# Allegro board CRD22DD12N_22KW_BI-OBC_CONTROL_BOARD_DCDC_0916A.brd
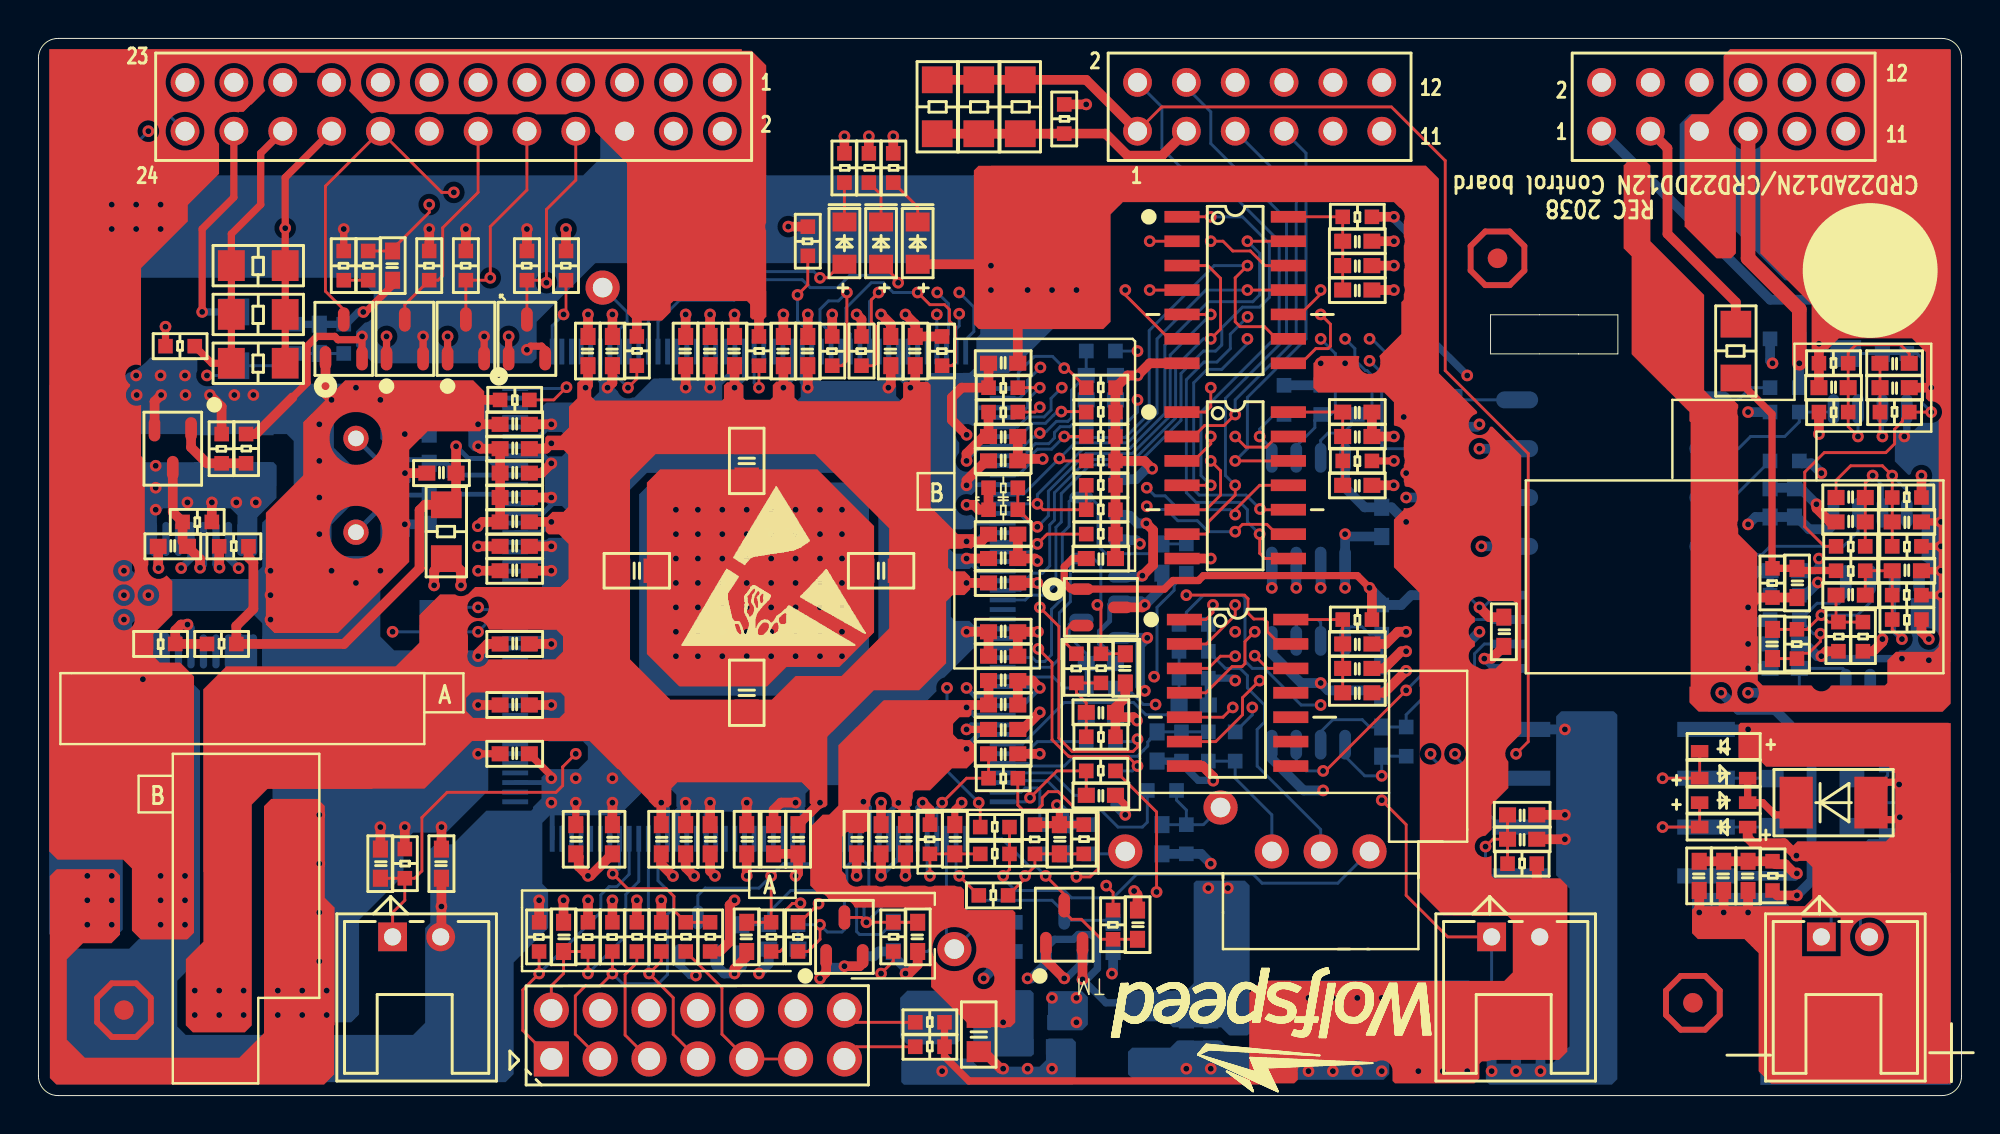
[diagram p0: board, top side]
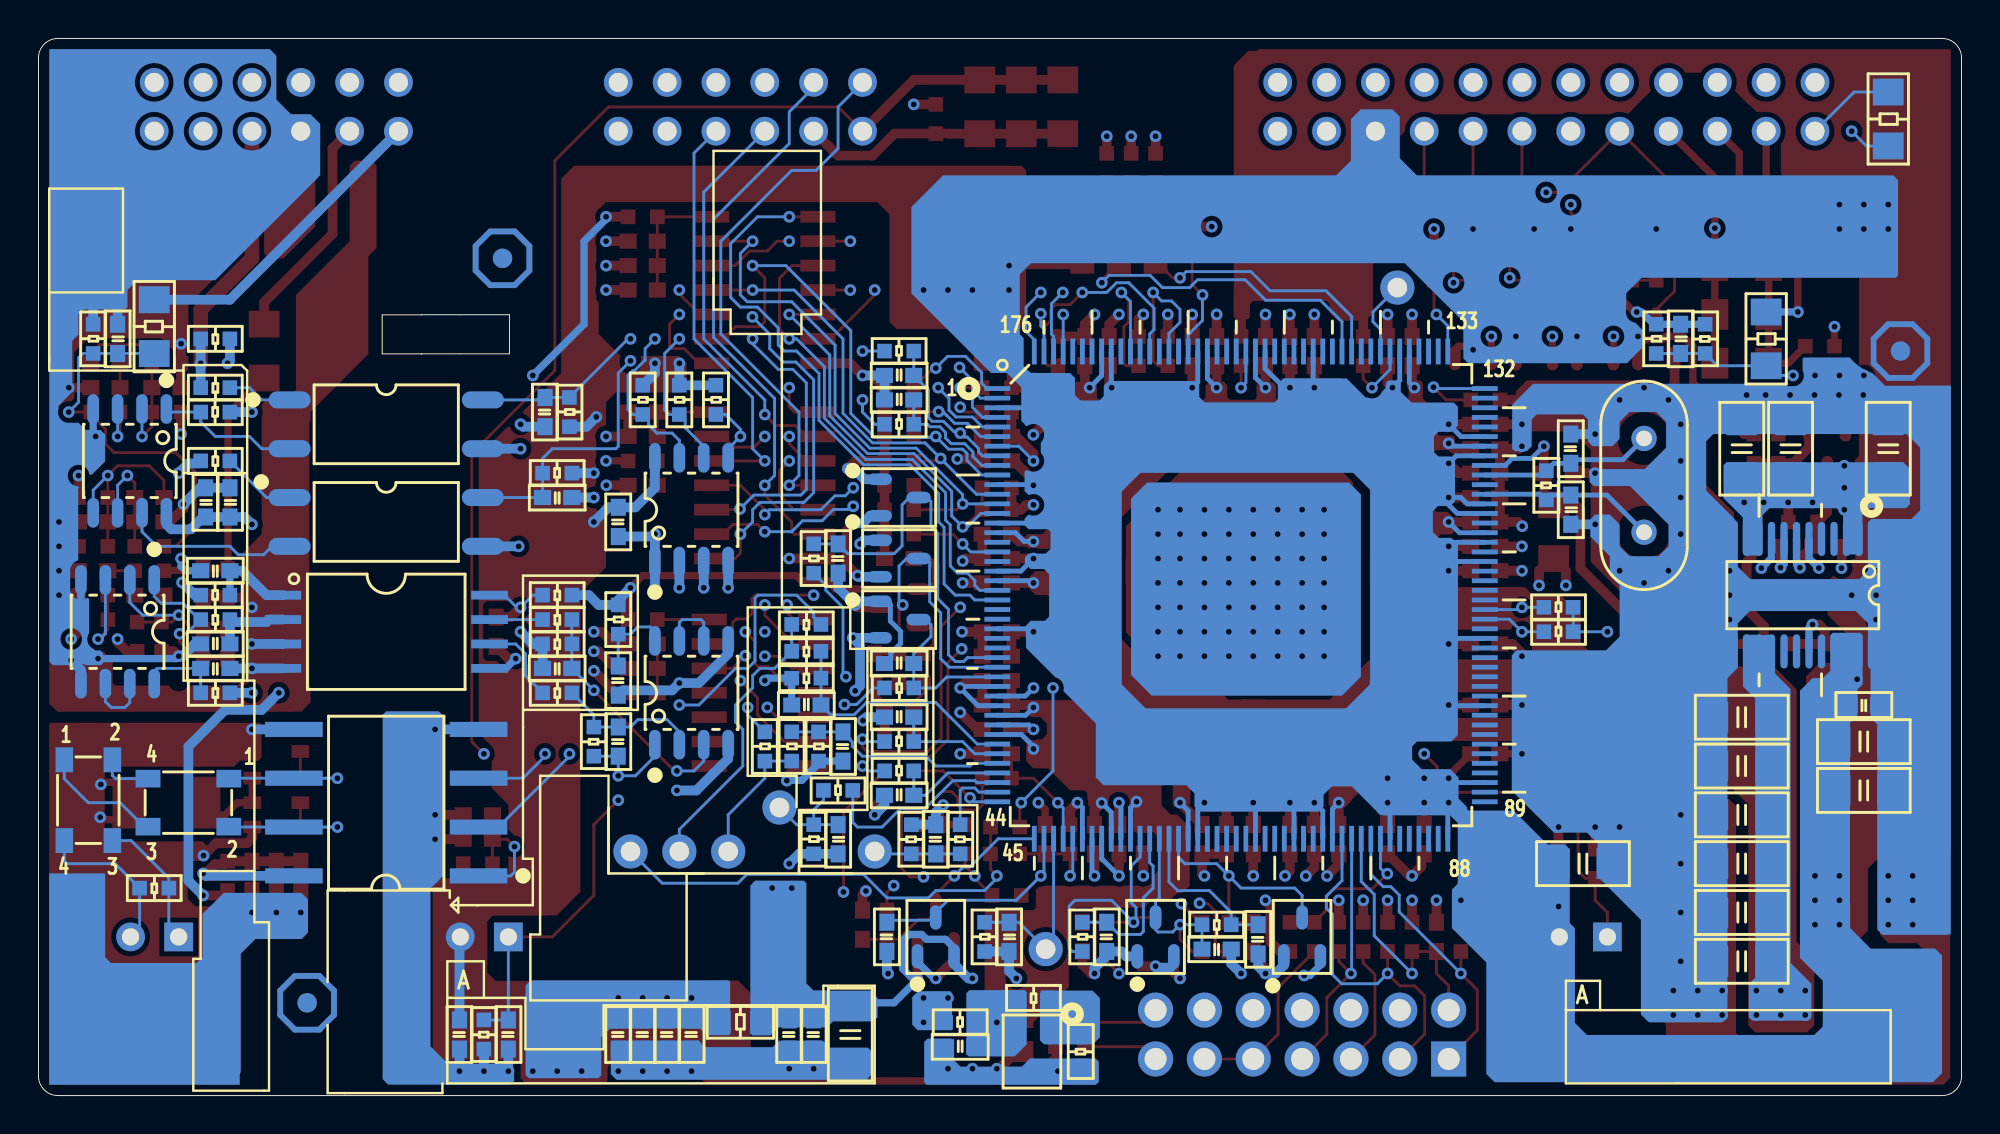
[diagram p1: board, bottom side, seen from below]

Outline 100 x 55 mm; copper layers: TOP, ART02, ART03, BOTTOM. Coordinates in mm from the lower left corner of the outline.
Outline path: 0,53.98 0,1.02 arc(0.3,0.3) 1.02,0 98.98,0 arc(99.7,0.3) 100,1.02 100,53.98 arc(99.7,54.7) 98.98,55 1.02,55 arc(0.3,54.7) 0,53.98 ; 75.51,40.62 80.08,40.62 80.08,40.62 82.13,40.62 82.13,38.59 80.08,38.59 80.08,38.59 75.51,38.59 75.51,40.62

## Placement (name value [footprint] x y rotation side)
AB  TP  [1MMTESTPOINT]  64.14 12.7 0 top
BC  TP  [1MMTESTPOINT]  66.67 12.7 0 top
C237  22n  [C0603]  91.44 26.67 90 top
C254  0.022n  [C0603]  20.32 30.48 90 bottom
C371  0.022n  [C0603]  20.32 33.66 270 bottom
C378  0.1u  [C0603]  27.3 8.26 90 top
C392  0.12n  [C0603]  50.16 34.29 0 top
C393  2.2n  [C0603]  55.24 15.62 0 bottom
C396  0.1u  [C0603]  69.85 29.84 270 bottom
C397  680p  [C0603]  52.07 2.54 0 bottom
C398  0.1u  [C0603]  69.85 3.17 270 bottom
C399  0.1u  [C0603]  68.58 3.17 270 bottom
C400  0.1u  [C0603]  67.31 3.17 270 bottom
C401  0.1u  [C0603]  66.04 3.17 270 bottom
C402  0.1u  [C0603]  60.96 3.17 270 bottom
C403  0.1u  [C0603]  59.69 3.17 270 bottom
C404  4.7u  [C1206]  57.78 3.17 270 bottom
C405  1u  [C0603]  78.11 3.17 270 bottom
C406  1u  [C0603]  20.95 12.06 270 top
C407  0.47u  [C0603]  75.56 3.17 270 bottom
C408  0.47u  [C0603]  55.24 22.48 0 bottom
C409  0.47u  [C0603]  17.78 12.06 90 top
C410  0.47u  [C0603]  58.42 27.94 270 bottom
C445  0.1u  [C0603]  90.81 27.3 180 bottom
C446  2.2n  [C0603]  90.81 23.5 0 bottom
C447  0.1u  [C0603]  76.2 24.13 90 top
C448  0.33n  [C0603]  73.03 22.23 180 bottom
C449  0.33n  [C0603]  69.85 18.41 270 bottom
C451  0.47u  [C0603]  69.85 21.59 270 bottom
C452  4.7n  [C0603]  57.15 8.89 90 top
C453  0.15n  [C0603]  97.16 27.3 180 top
C454  0.15n  [C0603]  94.23 26.04 180 top
C455  0.15n  [C0603]  90.17 23.5 270 top
C457  0.47u  [C0603]  90.81 22.23 180 bottom
C458  0.47n  [C0603]  96.52 36.83 0 top
C459  0.1u  [C0603]  93.34 36.83 180 top
C460  0.15n  [C0603]  96.52 38.1 0 top
C462  0.47u  [C0603]  90.04 30.86 90 bottom
C463  0.12n  [C0603]  73.66 35.56 270 bottom
C464  0.12n  [C0603]  73.03 31.11 180 bottom
C465  0.47n  [C0603]  94.23 29.84 180 top
C466  0.15n  [C0603]  94.23 31.11 180 top
C467  0.12n  [C0603]  97.16 29.84 0 top
C471  1u  [C0603]  77.15 14.61 0 top
C472  0.1u  [C0603]  77.15 13.34 0 top
C473  1u  [C0603]  86.36 11.43 270 top
C474  0.1u  [C0603]  88.9 11.43 270 top
C475  0.01u  [C0603]  87.63 11.43 270 top
C488  2.2n  [C0603]  53.09 13.34 90 top
C489  4.7n  [C0603]  55.88 8.26 270 bottom
C492  0.01u  [C0603]  55.24 19.94 0 top
C493  0.01u  [C0603]  56.52 22.23 270 top
C494  0.1u  [C0603]  55.24 27.94 0 top
C496  10u  [C1206]  11.43 33.66 90 bottom
C497  10u  [C1206]  8.89 33.66 90 bottom
C499  0.1u  [C0603]  5.08 20.32 180 bottom
C500  10u  [C1206]  5.08 18.41 180 bottom
C501  10u  [C1206]  5.08 15.88 180 bottom
C504  10u  [C1206]  3.81 33.66 90 bottom
C505  0.1u  [C0603]  6.99 28.57 180 top
C506  10u  [C1206]  19.68 12.06 180 bottom
C507  10u  [C1206]  11.43 14.61 0 bottom
C508  10u  [C1206]  11.43 12.06 0 bottom
C509  10u  [C1206]  11.43 17.14 0 bottom
C510  10u  [C1206]  11.43 9.53 0 bottom
C511  10u  [C1206]  11.43 6.99 0 bottom
C512  2.2u  [C0805]  36.83 33.02 270 top
C513  2.2u  [C0805]  43.81 27.3 180 top
C514  2.2u  [C0805]  36.83 20.95 90 top
C515  2.2u  [C0805]  31.11 27.3 0 top
C516  10u  [C1206]  11.43 19.68 0 bottom
C519  22n  [C0603]  20.95 32.38 180 top
C520  0.1u  [C0603]  50.16 38.1 180 top
C521  2.2u  [C0603]  50.16 19.05 0 top
C522  2.2u  [C0603]  45.59 38.73 270 top
C523  2.2u  [C0603]  44.32 38.73 270 top
C524  2.2u  [C0603]  40.01 38.73 270 top
C525  2.2u  [C0603]  38.73 38.73 270 top
C526  2.2u  [C0603]  36.2 38.73 270 top
C527  2.2u  [C0603]  34.92 38.73 270 top
C528  2.2u  [C0603]  33.66 38.73 270 top
C529  2.2u  [C0603]  29.84 38.73 270 top
C530  2.2u  [C0603]  28.57 38.73 270 top
C531  2.2u  [C0603]  24.77 34.92 180 top
C532  2.2u  [C0603]  24.77 33.66 180 top
C533  2.2u  [C0603]  24.77 32.38 180 top
C534  2.2u  [C0603]  24.77 31.11 180 top
C535  2.2u  [C0603]  24.77 29.84 180 top
C536  2.2u  [C0603]  24.77 28.57 180 top
C537  2.2u  [C0603]  24.77 27.3 180 top
C538  2.2u  [C0603]  24.77 23.5 180 top
C539  2.2u  [C0603]  24.77 20.32 180 top
C540  2.2u  [C0603]  24.77 17.78 180 top
C541  2.2u  [C0603]  27.94 13.34 90 top
C542  2.2u  [C0603]  29.84 13.34 90 top
C543  2.2u  [C0603]  32.38 13.34 90 top
C544  2.2u  [C0603]  33.66 13.34 90 top
C545  2.2u  [C0603]  34.92 13.34 90 top
C546  2.2u  [C0603]  36.83 13.34 90 top
C547  2.2u  [C0603]  38.23 13.34 90 top
C548  2.2u  [C0603]  39.5 13.34 90 top
C549  2.2u  [C0603]  45.09 13.34 90 top
C550  2.2u  [C0603]  43.81 13.34 90 top
C551  2.2u  [C0603]  42.55 13.34 90 top
C552  0.1u  [C0603]  50.16 22.86 0 top
C553  0.1u  [C0603]  50.16 33.02 180 top
C554  2.2u  [C0603]  50.16 29.21 180 top
C555  0.1u  [C0603]  50.16 27.94 180 top
C556  2.2u  [C0603]  50.16 26.67 180 top
C557  0.1u  [C0603]  50.16 24.13 180 top
C558  2.2u  [C0603]  50.16 21.59 180 top
C559  2.2u  [C0603]  50.16 20.32 180 top
C560  0.1u  [C0603]  68.58 35.56 0 top
C561  0.01u  [C0603]  68.58 31.75 0 top
C562  1u  [C0603]  68.58 34.29 0 top
C563  0.1u  [C0603]  68.58 23.5 0 top
C564  0.01u  [C0603]  68.58 20.95 0 top
C565  1u  [C0603]  68.58 22.23 0 top
C566  0.47u  [C0603]  91.31 30.86 90 bottom
C592  2.2u  [C0805]  48.9 3.17 270 top
C593  120p  [C0603]  45.72 8.26 270 top
C594  0.47n  [C0603]  95.89 39.37 90 bottom
C595  2.2n  [C0603]  44.45 8.26 270 bottom
C596  120p  [C0603]  38.73 7.62 180 bottom
C597  2.2n  [C0603]  36.58 8.13 270 bottom
C598  2.2n  [C0603]  55.24 15.62 0 top
C600  0.1u  [C0603]  68.58 43.18 0 top
C601  0.01u  [C0603]  68.58 41.91 0 top
C602  1u  [C0603]  68.58 44.45 0 top
C687  0.01u  [C0603]  49.53 8.26 90 bottom
C690  0.01u  [C0603]  53.34 13.34 270 bottom
C691  0.01u  [C0603]  58.42 13.34 90 bottom
C693  0.12n  [C0603]  55.24 36.2 0 bottom
C694  2.2n  [C0603]  55.24 19.68 0 bottom
C695  0.12n  [C0603]  55.24 37.47 0 bottom
C696  2.2n  [C0603]  50.16 17.78 0 top
C697  0.12n  [C0603]  18.41 43.18 270 top
C698  2.2n  [C0603]  14.61 39.37 90 bottom
C699  1n  [C0603]  36.83 8.26 270 top
C700  0.1u  [C0603]  60.07 20.32 0 bottom
C701  0.1u  [C0603]  58.17 18.16 270 bottom
C702  0.1u  [C0603]  47.65 13.34 90 top
CA  TP  [1MMTESTPOINT]  69.22 12.7 0 top
D84  BAV99  [SOT-23]  55.24 31.11 270 bottom
D85  BAV99  [SOT-23]  55.24 27.94 270 bottom
D86  BAV99  [SOT-23]  34.29 8.26 180 bottom
D89  BAV99  [SOT-23]  53.34 8.89 0 top
D90  BAV99  [SOT-23]  41.91 8.26 180 bottom
D92  BAV99  [SOT-23]  55.24 24.77 270 bottom
D95  BAV99  [SOT-23]  15.88 39.37 0 top
D102  RC-CL-170R-0805  [LED0805]  41.91 44.35 90 top
D103  RC-CL-170R-0805  [LED0805]  43.81 44.35 90 top
D104  RC-CL-170R-0805  [LED0805]  45.72 44.35 90 top
D110  BAS21WS-TP  [SOD-323]  87.63 13.97 180 top
D111  SMBJ15CA  [SMB]  93.34 15.24 180 top
D112  BAS21WS-TP  [SOD-323]  87.63 15.24 0 top
D113  BAS21WS-TP  [SOD-323]  87.63 17.91 180 top
D114  BAS21WS-TP  [SOD-323]  87.63 16.51 0 top
D115  BAV99  [SOT-23]  53.34 8.26 180 bottom
D124  BAV99  [SOT-23]  25.4 39.37 0 top
D125  BAV99  [SOT-23]  22.23 39.37 0 top
D126  BAV99  [SOT-23]  19.05 39.37 0 top
D127  BAV99  [SOT-23]  41.91 8.26 0 top
DAC_1  TP  [1MMTESTPOINT]  47.62 7.62 180 bottom
DAC_4  TP  [1MMTESTPOINT]  56.52 12.7 0 bottom
DAC_5  TP  [1MMTESTPOINT]  61.47 14.99 180 bottom
DAC_6  TP  [1MMTESTPOINT]  29.34 42.04 180 bottom
J2  PIN2*12-2.54-F  [CON_2MM54_12X2]  21.59 51.44 180 top
J3  PIN2*6-2.54-F  [CON_2MM54_6X2]  63.5 51.44 0 top
J4  PIN2*6-2.54-F  [CON_2MM54_6X2]  87.63 51.44 0 top
J5  2*7P 2.54  [CON_2MM54_7X2]  34.29 3.17 180 top
J11  XHB2.54-2P-F  [CON_2MM54_2X1]  92.71 8.26 180 top
J17  1*2P  [CONNECT_2MM54_2X1]  75.56 8.26 180 top
J18  1*2P  [CONNECT_2MM54_2X1]  18.41 8.26 180 top
L21  33uH 0.2A  [R0805]  63.5 3.81 0 bottom
NOREF  -  []  38.34 26.64 0 top
NOREF#2  #VAL  [unnamed#2]  4.45 4.45 0 top
NOREF#3  -  []  346.48 2.43 0 top
NOREF#4  -  []  95.25 42.93 0 top
NOREF#5  -  []  187.11 64.82 0 top
NOREF#6  -  []  1.02 0 90 top
NOREF#7  #VAL  [unnamed#2]  75.87 43.56 0 top
NOREF#8  -  []  0.01 -3.22 0 top
NOREF#9  -  []  280.71 1.57 0 top
NOREF#10  -  []  0.01 -5.17 0 top
NOREF#11  #VAL  [unnamed#2]  86.03 4.83 0 top
NOREF#12  -  []  2 -5 90 top
NOREF#13  #VAL  [unnamed#2]  3.17 38.73 180 bottom
NOREF#14  #VAL  [unnamed#2]  75.87 43.56 180 bottom
NOREF#15  #VAL  [unnamed#2]  86.03 4.83 180 bottom
Q1  2N7002/SOT  [SOT-23]  6.99 33.66 180 top
R49  620K  [R1206]  3.81 50.81 90 bottom
R58  24K  [R0603]  51.82 13.34 270 top
R133  12K  [R0603]  90.17 26.67 270 top
R221  1M  [R0603]  21.59 31.75 270 bottom
R327  1R  [R0603]  31.11 38.73 90 top
R400  1R  [R0603]  37.47 38.73 90 top
R404  10k  [R0603]  26.04 8.26 270 top
R405  10k  [R0603]  29.84 8.26 270 top
R406  10k  [R0603]  32.38 8.26 270 top
R407  10k  [R0603]  34.92 8.26 90 top
R408  0  [R0603]  33.66 8.26 90 top
R409  0  [R0603]  31.11 8.26 90 top
R410  470  [R0603]  28.57 8.26 270 top
R411  2.2k  [R0603]  46.35 3.81 180 top
R412  2.2k  [R0603]  46.35 2.54 180 top
R414  2k  [R0603]  55.24 34.29 180 top
R415  2k  [R0603]  55.24 33.02 180 top
R416  2k  [R0603]  55.24 30.48 180 top
R417  2k  [R0603]  50.16 30.48 0 top
R418  2k  [R0603]  41.27 38.73 270 top
R419  2k  [R0603]  40.01 44.45 270 top
R420  2k  [R0603]  46.99 38.73 270 top
R421  2k  [R0603]  42.8 38.73 270 top
R422  2k  [R0603]  55.24 29.21 180 top
R423  2k  [R0603]  55.24 36.83 180 top
R424  2k  [R0603]  50.16 36.83 0 top
R425  2k  [R0603]  55.24 35.56 180 top
R431  1k  [R0603]  50.16 35.56 0 top
R432  1k  [R0603]  55.24 16.89 0 bottom
R437  10k  [R0603]  64.77 36.2 90 bottom
R438  10k  [R0603]  66.67 36.2 90 bottom
R439  10k  [R0603]  68.58 36.2 90 bottom
R440  200  [R0603]  52.07 3.81 0 bottom
R441  1.5k  [R0603]  48.26 5.08 180 bottom
R442  4.7k  [R0603]  45.8 2.29 270 bottom
R443  2k  [R0603]  41.91 48.26 90 top
R444  2k  [R0603]  43.18 48.26 90 top
R445  2k  [R0603]  44.45 48.26 90 top
R446  10k  [R0603]  76.83 3.17 270 bottom
R447  3.3k  [R0603]  55.24 21.21 180 bottom
R448  10k  [R0603]  19.05 12.06 90 top
R449  3.3k  [R0603]  59.69 27.94 90 bottom
R482  2k  [R0603]  90.81 24.77 180 bottom
R483  10k  [R0603]  73.03 24.77 180 bottom
R484  10k  [R0603]  73.03 23.5 180 bottom
R485  10k  [R0603]  73.03 20.95 180 bottom
R486  10k  [R0603]  71.12 18.41 270 bottom
R487  2k  [R0603]  55.88 8.89 270 top
R488  150k  [R0603]  94.23 27.3 0 top
R489  100k  [R0603]  97.16 26.04 180 top
R491  100k  [R0603]  91.44 23.5 270 top
R492  1M  [R0603]  97.16 24.77 0 top
R493  1M  [R0603]  94.87 23.88 90 top
R494  150k  [R0603]  93.6 23.88 90 top
R495  2k  [R0603]  96.52 35.56 180 top
R496  2.2k  [R0603]  93.34 35.56 0 top
R497  2k  [R0603]  93.34 38.1 180 top
R500  3K  [R0603]  90.81 36.83 180 bottom
R502  3.9k  [R0603]  72.39 35.56 90 bottom
R503  3K  [R0603]  90.81 33.02 180 bottom
R505  3.9k  [R0603]  73.03 32.38 0 bottom
R506  1k  [R0603]  94.23 28.57 0 top
R507  15k  [R0603]  97.16 31.11 180 top
R508  4k  [R0603]  97.16 28.57 0 top
R514  620  [R0603]  20.95 24.13 0 bottom
R515  10k  [R0603]  20.95 25.4 0 bottom
R516  0  [R0603]  90.17 11.43 90 top
R517  120  [R0603]  93.98 10.79 180 bottom
R528  24k  [R0603]  54.36 13.34 90 top
R529  1k  [R0603]  49.66 10.41 180 top
R532  100  [R0603]  53.98 22.23 270 top
R533  470k  [R0603]  55.24 18.67 0 top
R534  3.3k  [R0603]  55.24 22.23 90 top
R536  10k  [R0603]  8.26 29.84 0 top
R537  1.5k  [R0603]  10.79 33.66 90 top
R538  12k  [R0603]  9.53 33.66 270 top
R540  100k  [R0603]  6.35 23.5 0 top
R541  0R  [R0603]  9.53 23.5 180 top
R546  10k  [R1206]  21.21 29.34 270 top
R547  0  [R0603]  10.16 28.57 180 top
R549  2.2R  [R0603]  68.58 33.02 0 top
R550  2.2R  [R0603]  68.58 24.77 0 top
R569  10k  [R0603]  90.81 35.56 0 bottom
R573  620k  [R1206]  88.27 38.73 270 top
R574  620k  [R1206]  93.98 40.01 270 bottom
R575  12K  [R0603]  97.16 39.37 90 bottom
R580  20R  [R1206]  51.05 51.44 90 top
R581  20R  [R1206]  48.9 51.44 90 top
R582  20R  [R1206]  46.74 51.44 90 top
R583  100  [R0603]  44.45 8.26 90 top
R588  0  [R0603]  53.34 50.81 90 top
R592  10R  [R0603]  90.81 20.95 180 bottom
R593  10R  [R0603]  90.81 26.04 0 bottom
R594  10R  [R0603]  73.03 26.04 180 bottom
R595  10R  [R0603]  69.85 24.77 90 bottom
R597  10R  [R0603]  90.81 39.37 180 bottom
R598  10R  [R0603]  77.15 12.06 180 top
R599  1k  [R0603]  45.72 8.26 90 bottom
R602  100  [R0603]  39.5 8.26 270 top
R603  20R  [R1206]  11.43 43.18 0 top
R604  20R  [R1206]  11.43 40.64 0 top
R605  20R  [R1206]  11.43 38.1 0 top
R606  1k  [R0603]  38.73 8.89 180 bottom
R607  1k  [R0603]  55.24 16.89 180 top
R608  1k  [R0603]  55.24 38.73 0 bottom
R610  2k  [R0603]  55.24 31.75 180 top
R611  2k  [R0603]  50.16 31.62 0 top
R612  2.2R  [R0603]  68.58 45.72 0 top
R673  100k  [R0603]  50.8 8.26 90 bottom
R678  1k  [R0603]  52.07 13.34 270 bottom
R679  1k  [R0603]  58.42 15.88 0 bottom
R680  100k  [R0603]  54.61 13.34 270 bottom
R681  100k  [R0603]  59.69 13.34 90 bottom
R683  1k  [R0603]  55.24 34.92 0 bottom
R684  1k  [R0603]  55.24 18.41 0 bottom
R685  10k  [R0603]  22.23 43.18 270 top
R686  1k  [R0603]  50.16 16.51 0 top
R687  10k  [R0603]  20.32 43.18 270 top
R688  10k  [R0603]  25.4 43.18 270 top
R689  1k  [R0603]  17.14 43.18 270 top
R691  10k  [R0603]  15.88 43.18 270 top
R692  24k  [R0603]  15.88 39.37 90 bottom
R693  1k  [R0603]  38.1 8.26 90 top
R694  620K  [R1206]  10.16 39.37 90 bottom
R695  24K  [R0603]  13.34 39.37 270 bottom
R696  1k  [R0603]  60.07 23.11 180 bottom
R697  NA  [R0603]  60.07 21.72 180 bottom
R698  1k  [R0603]  60.83 18.16 90 bottom
R699  NA  [R0603]  59.44 18.16 90 bottom
R700  1k  [R0603]  49.73 12.57 180 top
R701  NA  [R0603]  46.35 13.34 270 top
R702  0  [R0603]  7.37 38.99 180 top
R703  2k  [R0603]  27.43 43.18 270 top
R704  0R  [R0603]  60.07 24.51 180 bottom
R705  0R  [R0603]  49.73 13.97 180 top
R706  0R  [R0603]  62.23 18.16 90 bottom
R707  2k  [R0603]  24.77 36.2 0 top
T1  TRNSFMR TV105  [4532]  92.2 15.24 0 bottom
T2  TRNSFMR TV105  [4532]  97.41 15.37 270 bottom
U9  AZ431  [SOT23_1-32]  48.34 2.29 0 bottom
U28  TMS320F28377D  [LQFP176-050-2424]  37.47 26.04 270 bottom
U32  24C16BT-I/SN  [SOIC-8]  66.04 30.48 90 bottom
U43  ACPL-C870-500E  [SSO-8]  81.92 24.13 270 bottom
U44  OPA2376  [SOIC-8]  95.89 24.13 270 bottom
U45  OPA2376  [SOIC-8]  66.04 20.95 90 bottom
U48  LM2903  [SOIC-8]  95.25 33.02 270 bottom
U53  1050  [SO-G8]  81.92 15.24 0 bottom
U55  LM50CIM3  [SOT-23]  55.24 25.4 270 top
U57  TPS70445PWP_TSSOP24  [TSSOP24]  8.26 26.04 270 bottom
U58  MC74VHCT50A_SOIC14  [SOIC14]  62.23 31.75 0 top
U59  MC74VHCT50A_SOIC14  [SOIC14]  62.35 20.95 0 top
U60  -  [TCLT1003]  81.92 34.92 180 bottom
U61  -  [TCLT1003]  81.92 29.84 180 bottom
U62  MC74VHCT50A_SOIC14  [SOIC14]  62.23 41.91 0 top
Y1  HLX32 20MHz  [TSX-3225]  16.51 31.75 270 bottom

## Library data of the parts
AB BC CA DAC_1 DAC_4-DAC_6 = 1MMTESTPOINT: User Part Number: HAMP; Tolerance: #TOL
C237 C254 C371 C378 C392 C393 C396-C403 C405-C410 C445-C449 C451-C455 C457-C460 C462-C467 C471-C475 C488 C489 C492-C494 C499 C505 C519-C566 C593-C598 C600-C602 C687 C690 C691 C693-C702 = C0603: Tolerance: #TOL; User Part Number: HAMP
C404 C496 C497 C500 C501 C504 C506-C511 C516 = C1206: Tolerance: #TOL; User Part Number: HAMP
C512-C515 C592 = C0805: Tolerance: #TOL; User Part Number: HAMP
D84-D86 D89 D90 D92 D95 D115 D124-D127 Q1 U55 = SOT-23: Tolerance: #TOL; User Part Number: HAMP
D102-D104 = LED0805: Tolerance: #TOL; User Part Number: HAMP
D110 D112-D114 = SOD-323: Tolerance: #TOL; User Part Number: HAMP
D111 = SMB: Tolerance: #TOL; User Part Number: HAMP
J2 = CON_2MM54_12X2: Tolerance: #TOL; User Part Number: HAMP
J3 J4 = CON_2MM54_6X2: Tolerance: #TOL; User Part Number: HAMP
J5 = CON_2MM54_7X2: Tolerance: #TOL; User Part Number: HAMP
J11 = CON_2MM54_2X1: Tolerance: #TOL; User Part Number: HAMP
J17 J18 = CONNECT_2MM54_2X1: Tolerance: #TOL; User Part Number: HAMP
L21 = R0805: Tolerance: #TOL; User Part Number: HAMP
NOREF#2 NOREF#7 NOREF#11 NOREF#13-NOREF#15 = -: Tolerance: #TOL; User Part Number: HAMP
R49 R546 R573 R574 R580-R582 R603-R605 R694 = R1206: Tolerance: #TOL; User Part Number: HAMP
R58 R133 R221 R327 R400 R404-R412 R414-R425 R431 R432 R437-R449 R482-R489 R491-R497 R500 R502 R503 R505-R508 R514-R517 R528 R529 R532-R534 R536-R538 R540 R541 R547 R549 R550 R569 R575 R583 R588 R592-R595 R597-R599 R602 R606-R608 R610-R612 R673 R678-R681 R683-R689 R691-R693 R695-R707 = R0603: Tolerance: #TOL; User Part Number: HAMP
T1 T2 = 4532: Tolerance: #TOL; User Part Number: HAMP
U9 = SOT23_1-32: Tolerance: #TOL; User Part Number: HAMP
U28 = LQFP176-050-2424: Tolerance: #TOL; User Part Number: HAMP
U32 U44 U45 U48 = SOIC-8: Tolerance: #TOL; User Part Number: HAMP
U43 = SSO-8: Tolerance: #TOL; User Part Number: HAMP
U53 = SO-G8: Tolerance: #TOL; User Part Number: HAMP
U57 = TSSOP24: Tolerance: #TOL; User Part Number: HAMP
U58 U59 U62 = SOIC14: Tolerance: #TOL; User Part Number: HAMP
U60 U61 = TCLT1003: Tolerance: #TOL; User Part Number: HAMP
Y1 = TSX-3225: Tolerance: #TOL; User Part Number: HAMP

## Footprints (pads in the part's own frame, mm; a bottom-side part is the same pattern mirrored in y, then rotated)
1MMTESTPOINT
  round 1.778 hole 1.016: 1(0,0)
4532
  rect 1.295x0.914 smd: 1(-2.1,-1.25) 2(-2.1,1.25) 3(2.1,1.25) 4(2.1,-1.25)
C0603
  rect 0.889x0.787 smd: 1(-0.76,0) 2(0.76,0)
C0805
  rect 1.092x1.27 smd: 1(-0.89,0) 2(0.89,0)
C1206
  rect 1.397x1.6 smd: 1(-1.4,0) 2(1.4,0)
CON_2MM54_2X1
  rect 1.499x1.499 hole 0.889: 1(0,0)
  round 1.499 hole 0.889: 2(-2.5,0)
CON_2MM54_6X2
  round 1.499 hole 0.991: 1(-6.35,-1.27) 2(-6.35,1.27) 3(-3.81,-1.27) 4(-3.81,1.27) 5(-1.27,-1.27) 6(-1.27,1.27) 7(1.27,-1.27) 8(1.27,1.27) 9(3.81,-1.27) 10(3.81,1.27) 11(6.35,-1.27) 12(6.35,1.27)
CON_2MM54_7X2
  rect 1.829x1.829 hole 1.143: 1(7.62,1.271)
  round 1.829 hole 1.143: 2(7.62,-1.271) 3(5.08,1.271) 4(5.08,-1.271) 5(2.54,1.271) 6(2.54,-1.271) 7(0,1.271) 8(0,-1.271) 9(-2.54,1.271) 10(-2.54,-1.271) 11(-5.08,1.271) 12(-5.08,-1.271) 13(-7.62,1.271) 14(-7.62,-1.271)
CON_2MM54_12X2
  round 1.499 hole 0.991: 1(-13.97,-1.27) 2(-13.97,1.27) 3(-11.43,-1.27) 4(-11.43,1.27) 5(-8.89,-1.27) 6(-8.89,1.27) 7(-6.35,-1.27) 8(-6.35,1.27) 9(-3.81,-1.27) 10(-3.81,1.27) 11(-1.27,-1.27) 12(-1.27,1.27) 13(1.27,-1.27) 14(1.27,1.27) 15(3.81,-1.27) 16(3.81,1.27) 17(6.35,-1.27) 18(6.35,1.27) 19(8.89,-1.27) 20(8.89,1.27) 21(11.43,-1.27) 22(11.43,1.27) 23(13.97,-1.27) 24(13.97,1.27)
CONNECT_2MM54_2X1
  rect 1.499x1.499 hole 0.889: 1(0,0)
  round 1.499 hole 0.889: 2(-2.5,0)
LED0805
  rect 0.991x1.245 smd: 1(1.1,0) 2(-1.1,0)
LQFP176-050-2424
  rect 8.636x8.636 smd: 0(0,0)
  rect 0.254x1.346 smd: 1(-10.75,-12.675) 2(-10.25,-12.675) 3(-9.75,-12.675) 4(-9.25,-12.675) 5(-8.75,-12.675) 6(-8.25,-12.675) 7(-7.75,-12.675) 8(-7.25,-12.675) 9(-6.75,-12.675) 10(-6.25,-12.675) 11(-5.75,-12.675) 12(-5.25,-12.675) 13(-4.75,-12.675) 14(-4.25,-12.675) 15(-3.75,-12.675) 16(-3.25,-12.675) 17(-2.75,-12.675) 18(-2.25,-12.675) 19(-1.75,-12.675) 20(-1.25,-12.675) 21(-0.75,-12.675) 22(-0.25,-12.675) 23(0.25,-12.675) 24(0.75,-12.675) 25(1.25,-12.675) 26(1.75,-12.675) 27(2.25,-12.675) 28(2.75,-12.675) 29(3.25,-12.675) 30(3.75,-12.675) 31(4.25,-12.675) 32(4.75,-12.675) 33(5.25,-12.675) 34(5.75,-12.675) 35(6.25,-12.675) 36(6.75,-12.675) 37(7.25,-12.675) 38(7.75,-12.675) 39(8.25,-12.675) 40(8.75,-12.675) 41(9.25,-12.675) 42(9.75,-12.675) 43(10.25,-12.675) 44(10.75,-12.675) 89(10.75,12.675) 90(10.25,12.675) 91(9.75,12.675) 92(9.25,12.675) 93(8.75,12.675) 94(8.25,12.675) 95(7.75,12.675) 96(7.25,12.675) 97(6.75,12.675) 98(6.25,12.675) 99(5.75,12.675) 100(5.25,12.675) 101(4.75,12.675) 102(4.25,12.675) 103(3.75,12.675) 104(3.25,12.675) 105(2.75,12.675) 106(2.25,12.675) 107(1.75,12.675) 108(1.25,12.675) 109(0.75,12.675) 110(0.25,12.675) 111(-0.25,12.675) 112(-0.75,12.675) 113(-1.25,12.675) 114(-1.75,12.675) 115(-2.25,12.675) 116(-2.75,12.675) 117(-3.25,12.675) 118(-3.75,12.675) 119(-4.25,12.675) 120(-4.75,12.675) 121(-5.25,12.675) 122(-5.75,12.675) 123(-6.25,12.675) 124(-6.75,12.675) 125(-7.25,12.675) 126(-7.75,12.675) 127(-8.25,12.675) 128(-8.75,12.675) 129(-9.25,12.675) 130(-9.75,12.675) 131(-10.25,12.675) 132(-10.75,12.675)
  rect 1.346x0.254 smd: 45(12.675,-10.75) 46(12.675,-10.25) 47(12.675,-9.75) 48(12.675,-9.25) 49(12.675,-8.75) 50(12.675,-8.25) 51(12.675,-7.75) 52(12.675,-7.25) 53(12.675,-6.75) 54(12.675,-6.25) 55(12.675,-5.75) 56(12.675,-5.25) 57(12.675,-4.75) 58(12.675,-4.25) 59(12.675,-3.75) 60(12.675,-3.25) 61(12.675,-2.75) 62(12.675,-2.25) 63(12.675,-1.75) 64(12.675,-1.25) 65(12.675,-0.75) 66(12.675,-0.25) 67(12.675,0.25) 68(12.675,0.75) 69(12.675,1.25) 70(12.675,1.75) 71(12.675,2.25) 72(12.675,2.75) 73(12.675,3.25) 74(12.675,3.75) 75(12.675,4.25) 76(12.675,4.75) 77(12.675,5.25) 78(12.675,5.75) 79(12.675,6.25) 80(12.675,6.75) 81(12.675,7.25) 82(12.675,7.75) 83(12.675,8.25) 84(12.675,8.75) 85(12.675,9.25) 86(12.675,9.75) 87(12.675,10.25) 88(12.675,10.75) 133(-12.675,10.75) 134(-12.675,10.25) 135(-12.675,9.75) 136(-12.675,9.25) 137(-12.675,8.75) 138(-12.675,8.25) 139(-12.675,7.75) 140(-12.675,7.25) 141(-12.675,6.75) 142(-12.675,6.25) 143(-12.675,5.75) 144(-12.675,5.25) 145(-12.675,4.75) 146(-12.675,4.25) 147(-12.675,3.75) 148(-12.675,3.25) 149(-12.675,2.75) 150(-12.675,2.25) 151(-12.675,1.75) 152(-12.675,1.25) 153(-12.675,0.75) 154(-12.675,0.25) 155(-12.675,-0.25) 156(-12.675,-0.75) 157(-12.675,-1.25) 158(-12.675,-1.75) 159(-12.675,-2.25) 160(-12.675,-2.75) 161(-12.675,-3.25) 162(-12.675,-3.75) 163(-12.675,-4.25) 164(-12.675,-4.75) 165(-12.675,-5.25) 166(-12.675,-5.75) 167(-12.675,-6.25) 168(-12.675,-6.75) 169(-12.675,-7.25) 170(-12.675,-7.75) 171(-12.675,-8.25) 172(-12.675,-8.75) 173(-12.675,-9.25) 174(-12.675,-9.75) 175(-12.675,-10.25) 176(-12.675,-10.75)
R0603
  rect 0.762x0.762 smd: 1(-0.76,0) 2(0.76,0)
R0805
  rect 0.991x1.194 smd: 1(-1,0) 2(1,0)
R1206
  rect 1.397x1.6 smd: 1(-1.4,0) 2(1.4,0)
SMB
  rect 1.727x2.692 smd: 1(-1.943,0) 2(1.943,0)
SO-G8
  rect 2.997x0.787 smd: 1(-4.8,3.81) 2(-4.8,1.27) 3(-4.8,-1.27) 4(-4.8,-3.81) 5(4.8,-3.81) 6(4.8,-1.27) 7(4.8,1.27) 8(4.8,3.81)
SOD-323
  rect 0.914x0.66 smd: 1(-1.25,0) 2(1.25,0)
SOIC14
  rect 1.829x0.61 smd: 1(-2.765,3.81) 2(-2.765,2.54) 3(-2.765,1.27) 4(-2.765,0) 5(-2.765,-1.27) 6(-2.765,-2.54) 7(-2.765,-3.81) 8(2.765,-3.81) 9(2.765,-2.54) 10(2.765,-1.27) 11(2.765,0) 12(2.765,1.27) 13(2.765,2.54) 14(2.765,3.81)
SOIC-8
  oval 1.549x0.61 smd: 1(-2.7,1.905) 2(-2.7,0.635) 3(-2.7,-0.635) 4(-2.7,-1.905) 5(2.7,-1.905) 6(2.7,-0.635) 7(2.7,0.635) 8(2.7,1.905)
SOT23_1-32
  oval 0.61x1.27 smd: 1(-0.95,-1.01) 2(0.95,-1.01) 3(0,1.01)
SOT-23
  oval 0.61x1.27 smd: 1(-0.95,-1.01) 2(0.95,-1.01) 3(0,1.01)
SSO-8
  rect 0.457x1.905 smd: 1(-1.905,-5.373) 2(-0.635,-5.373) 3(0.635,-5.373) 4(1.905,-5.373) 5(1.905,5.373) 6(0.635,5.373) 7(-0.635,5.373) 8(-1.905,5.373)
TCLT1003
  oval 2.184x0.889 smd: 1(-5.025,1.27) 2(-5.025,-1.27) 3(5.025,-1.27) 4(5.025,1.27)
TSSOP24
  oval 1.778x0.381 smd: 1(-2.925,3.575) 2(-2.925,2.925) 3(-2.925,2.275) 4(-2.925,1.625) 5(-2.925,0.975) 6(-2.925,0.325) 7(-2.925,-0.325) 8(-2.925,-0.975) 9(-2.925,-1.625) 10(-2.925,-2.275) 11(-2.925,-2.925) 12(-2.925,-3.575) 13(2.925,-3.575) 14(2.925,-2.925) 15(2.925,-2.275) 16(2.925,-1.625) 17(2.925,-0.975) 18(2.925,-0.325) 19(2.925,0.325) 20(2.925,0.975) 21(2.925,1.625) 22(2.925,2.275) 23(2.925,2.925) 24(2.925,3.575)
  rect 1.651x3.937 smd: 25(0,0)
TSX-3225
  round 1.321 hole 0.813: 1(-2.44,0) 2(2.44,0)
unnamed#2
  round 1.016 smd: 1(0,0)

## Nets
AGND: C254.1 C371.1 C378.2 C392.2 C393.2 C396.2 C397.2 C398.2 C399.2 C400.2 C401.2 C402.2 C403.2 C404.2 C405.2 C406.1 C407.2 C408.2 C409.2 C410.2 C447.1 C448.1 C451.2 C452.2 C463.2 C464.2 C471.2 C472.2 C488.2 C489.2 C492.2 C493.2 C494.2 C496.2 C497.2 C499.2 C500.2 C501.2 C504.2 C505.2 C506.2 C507.2 C508.2 C509.2 C510.2 C511.2 C512.2 C513.2 C514.2 C515.2 C516.2 C519.2 C520.2 C521.2 C522.1 C523.1 C524.1 C525.1 C526.1 C527.1 C528.1 C529.1 C530.1 C531.2 C532.2 C533.2 C534.2 C535.2 C536.2 C537.2 C538.2 C539.2 C540.2 C541.1 C542.1 C543.1 C544.1 C545.1 C546.1 C547.1 C548.1 C549.1 C550.1 C551.1 C552.2 C553.1 C554.1 C555.1 C556.1 C557.1 C558.1 C559.1 C560.2 C561.2 C562.2 C563.2 C564.2 C565.2 C592.2 C593.2 C595.2 C596.2 C597.2 C598.2 C600.2 C601.2 C602.2 C687.1 C690.1 C691.1 C693.2 C694.2 C695.2 C696.2 C697.2 C698.2 C699.2 C700.2 C701.2 C702.2 D84.1 D85.1 D86.1 D89.1 D90.1 D92.1 D95.1 D115.1 D124.1 D125.1 D126.1 D127.1 J2.13 J2.21 J3.6 J3.8 J5.4 J5.6 J5.8 J5.10 J5.12 Q1.2 R58.1 R410.1 R414.1 R415.1 R416.1 R417.1 R418.1 R419.1 R420.1 R421.1 R422.1 R423.1 R424.1 R425.1 R442.2 R443.2 R444.2 R445.2 R446.2 R448.2 R484.1 R528.2 R533.2 R538.1 R588.2 R610.1 R611.1 R673.1 R680.1 R681.1 R692.2 R695.1 R697.1 R699.1 R701.1 R702.2 R703.1 R707.1 U9.3 U28.0 U28.32 U28.33 U28.34 U28.50 U28.51 U28.52 U32.1 U32.2 U32.3 U32.4 U43.5 U45.4 U45.5 U53.4 U55.3 U57.1 U57.6 U57.9 U57.12 U57.13 U57.24 U57.25 U58.7 U59.7 U60.3 U61.3 U62.7
SGND: C237.1 C445.1 C446.2 C453.1 C457.2 C458.2 C459.2 C462.2 C465.2 C467.2 C566.2 C594.2 J4.5 R133.2 R489.1 R494.1 R497.2 R508.2 R575.2 U43.3 U43.4 U44.4 U44.5 U48.4
VDD: C507.1 C508.1 C509.1 C510.1 C511.1 C512.1 C513.1 C514.1 C515.1 C516.1 C522.2 C525.2 C526.2 C530.2 C532.1 C535.1 C543.2 C548.2 C554.2 C556.2 U28.16 U28.21 U28.61 U28.76 U28.117 U28.126 U28.137 U28.153 U28.158 U28.169 U57.14 U57.15 U57.16
/TRST_P: C378.1 J5.2 R410.2 U28.79
/WP_PFC: R439.1 U28.175 U32.7
_AC_LA_ADC: C393.1 R432.1 U28.41
_AC_LA_OC: C392.1 R431.1 U28.7
_AC_LB_ADC: C694.1 R684.1 U28.39
_AC_LB_OC: C693.1 R683.1 U28.9
_AC_LC_ADC: C696.1 R686.1 U28.48
_AC_LC_OC: C695.1 C697.1 R608.1 R689.1 U28.8
_AD_DCINPUT: C489.1 D115.3 R529.2 U28.46
_AD_DCINPUT_OV: C699.1 D86.3 R693.2 U28.60
_AD_DCTEMP: C408.1 D92.3 R447.2 U28.31
_AD_SRTEMP: C410.1 D84.3 R449.2 U28.29
AC_LA_ADC: J2.15 R432.2
AC_LA_OC: D124.3 J2.8 R431.2 R688.2
AC_LAB_SENSE_ADC: AB.1 R698.1 R706.1
AC_LB_ADC: J2.17 R684.2
AC_LB_OC: D125.3 J2.10 R683.2 R685.2
AC_LBC_SENSE_ADC: BC.1 R696.1 R704.1
AC_LC_ADC: J2.19 R686.2
AC_LC_OC: D126.3 J2.12 R608.2 R687.2
AC_LCA_SENSE_ADC: CA.1 R700.1 R705.1
AD_AIR_TEMP: C493.1 D85.3 R534.2 U28.30
AD_DCVOLT1: C452.1 D89.3 R487.2 U28.45
CAN5V_GND: C473.2 C474.2 C475.2 D110.1 D111.1 D113.1 J4.11 U53.5
CAN_5V: J4.12 R516.1
CANRX: R514.2 U28.108 U53.2
CANTX: R515.2 U28.109 U53.3
CS: J3.1 R580.2 R581.2 R582.2 R583.1
CS_ADC: C593.1 D127.3 R583.2 R599.1 U28.56
CS_PRI: J2.18 R602.1 R603.2 R604.2 R605.2
CS_RTN: J3.3 R580.1 R581.1 R582.1 R588.1
CS_RTN_PRI: J2.20 R603.1 R604.1 R605.1 R702.1
DC-OV: J2.22 R694.2
DC_FB: J2.24 R49.2
DCOVP: C463.1 R502.2 U28.176 U60.4
DCPWM1A_1H: J3.4 U58.6
DCPWM1A_1HH: R419.2 U28.160 U58.5
DCPWM1A_1L: J3.2 U58.4
DCPWM1A_1LL: R418.2 U28.162 U58.3
DCPWM2A_2H: J3.7 U58.12
DCPWM2A_2HH: R420.2 U28.164 U58.13
DCPWM2A_2L: J3.5 U58.2
DCPWM2A_2LL: R421.2 U28.166 U58.1
DCSHORT: C464.1 R505.2 U28.5 U61.4
DCVOLT1: C455.2 R482.1 R491.2 U44.1
IOUT_ADC: J2.14 R607.1
OUTPUT_OC: D95.3 J2.16 U28.2
OUTPUT_OC_17227068: R689.2 R691.2
P_ADREF3.2V: C397.1 C549.2 C551.2 C558.2 C559.2 C592.1 R440.1 R441.1 U9.2 U28.35 U28.37 U28.53 U28.55
P_SCL: R438.1 U28.174 U32.6
P_SDA: R437.1 U28.173 U32.5
P_WD_GREEN: D102.2 U28.143
P_WD_RED: D103.2 U28.144
PCS_ADC: C596.1 D90.3 R602.2 R606.1 U28.58
PCS_ADC1: C597.1 R606.2 U28.59
PWM1A: J2.1 U62.8
PWM1AA: R414.2 U28.10 U62.9
PWM1B: J2.3 U62.10
PWM1BB: R415.2 U28.12 U62.11
PWM1C: J2.5 U62.12
PWM1CC: R416.2 R610.2 U28.13 U62.13
PWM1D: J2.7 U62.6
PWM1DD: R417.2 R611.2 U28.14 U62.5
PWM1E: J2.9 U62.4
PWM1EE: U28.22 U62.3
PWM1F: J2.11 U62.2
PWM1FF: U28.23 U62.1
RLYCTRL1: J2.2 U58.10
RLYCTRL2: J2.4 U58.8
RLYCTRL11: R703.2 U28.133 U58.11
RLYCTRL22: R707.2 U28.132 U58.9
SR-PWM-A: J3.9 U59.12
SR-PWM-AA: R422.2 U28.18 U59.13
SR-PWM-B: J3.10 U59.2
SR-PWM-BB: R423.2 U28.1 U59.1
SR-PWM-C: J3.11 U59.4
SR-PWM-CC: R424.2 U28.4 U59.3
SR-PWM-D: J3.12 U59.6
SR-PWM-DD: R425.2 U28.6 U59.5
TCK_P: R407.2 R408.2 U28.81
TDI_P: J5.3 R405.2 U28.77
TDO_P: J5.7 R406.2 U28.78
TEST: DAC_6.1 U28.140
TMS_P: J5.1 R404.2 U28.80
VO1+: J4.1 R574.1
VO2+: J4.3 R573.1
VP3.3A: C402.1 C403.1 C404.1 C521.1 C550.2 D84.2 D85.2 D86.2 D89.2 D90.2 D92.2 D115.2 D127.2 L21.1 U28.36 U28.54
VP3.3D: C396.1 C398.1 C399.1 C400.1 C401.1 C405.1 C406.2 C499.1 C500.1 C501.1 C506.1 C520.1 C523.2 C524.2 C527.2 C528.2 C529.2 C531.1 C533.1 C534.1 C536.1 C537.1 C538.1 C539.1 C540.1 C541.2 C542.2 C544.2 C545.2 C546.2 C547.2 C552.1 C553.2 C555.2 C557.2 D95.2 D104.2 D124.2 D125.2 D126.2 J2.6 J17.2 J18.2 L21.2 R327.2 R400.2 R404.1 R405.1 R406.1 R407.1 R409.2 R411.1 R412.1 R437.2 R438.2 R439.2 R502.1 R505.1 R537.2 R540.1 R546.2 R598.1 R685.1 R687.1 R688.1 R691.1 U28.3 U28.11 U28.15 U28.20 U28.26 U28.62 U28.68 U28.72 U28.75 U28.82 U28.88 U28.91 U28.99 U28.106 U28.114 U28.116 U28.119 U28.120 U28.125 U28.127 U28.138 U28.147 U28.152 U28.159 U28.168 U32.8 U57.21 U57.22 U57.23
VP+5V: C494.1 C496.1 C497.1 C504.1 J2.23 R440.2 R536.2 R549.2 R550.2 R594.2 R595.2 R612.2 U55.1 U57.2 U57.3 U57.10 U57.11
VS+5V: J4.7 R492.2 R493.1 R496.1 R500.1 R503.1 R507.1 R569.1 R592.2 R593.2 R597.1
X1: C371.2 R221.1 U28.123 Y1.1
X2: C254.2 R221.2 U28.121 Y1.2
XRS: C519.1 R541.1 R546.1 R547.1 U28.124
N16777869: J5.9 J5.11 R408.1
N16778586: C702.1 R700.2 R701.2 U28.49
N16779815: R327.1 U28.139
N16809513: J5.5 R409.1
N16810933: J5.13 R412.2
N16810951: J5.14 R411.2
N16830570: R441.2 R442.1 U9.1
N16833081: D102.1 R443.1
N16833084: D103.1 R444.1
N16833087: D104.1 R445.1
N16835391: C407.1 J17.1 R446.1 R447.1
N16836592: C409.1 J18.1 R448.1 R449.1
N16848574: C446.1 R482.2 U43.2
N16848598: C445.2 R593.1 U43.1
N16848614: C447.2 R594.1 U43.8
N16848642: R483.1 U43.7
N16848644: C448.2 R483.2 R484.2 U45.3
N16848814: R485.1 U43.6
N16848816: C449.1 R485.2 R486.1 U45.2
N16848832: C449.2 R486.2 R487.1 U45.1
N16848970: U44.6 U44.7
N16848978: C453.2 C454.1 R488.2 R489.2 R492.1 U44.3
N16848994: C454.2 C455.1 R491.1 R493.2 R494.2 U44.2
N16849016: C457.1 R592.1 U44.8
N16851028: U45.6 U45.7
N16851046: C451.1 R595.1 U45.8
N16853569: C458.1 C460.1 R495.2 U48.3
N16853931: C459.1 C460.2 R496.2 R497.1 U48.2
N16853972: R569.2 U48.1 U60.2
N16854025: C462.1 C566.1 R597.2 U48.8
N16854569: R500.2 U60.1
N16855013: C466.2 C467.1 R507.2 R508.1 U48.5
N16855828: C465.1 C466.1 R506.2 U48.6
N16855912: U48.7 U61.2
N16855916: R503.2 U61.1
N16860426: C471.1 C472.1 R514.1 R515.1 R598.2 U53.1
N16860580: C473.1 C474.1 C475.1 R516.2 U53.8
N16860640: D110.2 D112.1 T1.2 U53.7
N16861242: J11.2 R517.1 T2.4
N16861249: D113.2 D114.1 T1.1 U53.6
N16861268: J11.1 R517.2 T2.3
N16861373: D111.2 D112.2 D114.2
N16900365: Q1.1 R537.1 R538.2
N16900541: C505.1 Q1.3 R536.1 U57.7
N16908509: R540.2 R541.2 U57.19
N16935004: R547.2 U57.8
N17022031: C560.1 C561.1 C562.1 R549.1 U58.14
N17025421: C563.1 C564.1 C565.1 R550.1 U59.14
N17096901: C237.2 R133.1 R488.1 R573.2
N17102058: C594.1 R495.1 R506.1 R574.2 R575.1
N17145229: C595.1 R599.2 U28.57
N17182974: C488.1 R49.1 R58.2 R528.1 R529.1
N17183073: C492.1 R532.2 R533.1 R534.1
N17183105: R532.1 U55.2
N17207390: C600.1 C601.1 C602.1 R612.1 U62.14
N17215412: R679.1 U28.42
N17215422: R678.1 U28.43
N17215466: C691.2 DAC_5.1 R679.2 R681.2
N17215490: C690.2 DAC_4.1 R678.2 R680.2
N17215663: C687.2 DAC_1.1 R673.2 U28.47
N17215880: C598.1 R607.2 U28.44
N17228521: C698.1 R692.1 R693.1 R694.1 R695.2
N17238784: J4.6 R705.2
N17238858: C700.1 R696.2 R697.2 U28.38
N17241205: C701.1 R698.2 R699.2 U28.40
N17279598: T1.3 T2.1
N17279601: T1.4 T2.2
N17282960: J4.4 R704.2
N17283298: J4.2 R706.2
N16779431153: R400.1 U28.154

Pads without a net: J4 8 9 10; NOREF#2 1; NOREF#7 1; NOREF#11 1; NOREF#13 1; NOREF#14 1; NOREF#15 1; U28 17 19 24 25 27 28 63 64 65 66 67 69 70 71 73 74 83 84 85 86 87 89 90 92 93 94 95 96 97 98 100 101 102 103 104 105 107 110 111 112 113 115 118 122 128 129 130 131 134 135 136 141 142 145 146 148 149 150 151 155 156 157 161 163 165 167 170 171 172; U57 4 5 17 18 20; U59 8 9 10 11

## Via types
v1: diameter 0.61, hole 0.305, TOP to BOTTOM, 508 vias

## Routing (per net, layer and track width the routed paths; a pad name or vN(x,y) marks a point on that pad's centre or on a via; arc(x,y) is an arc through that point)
AGND: length 248.8
  TOP w0.381: C488.2 R58.1 ; C488.2 53.09,14.99 v1(52.96,15.11) ; C488.2 R528.2 ; v1(48.01,15.24) 47.65,14.88 C702.2 ; D126.1 v1(18.1,39.5) ; C540.2 v1(22.86,17.78) ; C697.2 18.41,42.16 17.02,40.76 v1(16.89,40.76) ; R702.2 v1(6.61,40) ; v1(56.52,14.61) 56.52,15.11 C598.2 ; D125.1 v1(21.28,39.5) ; D124.1 v1(24.45,39.5)
  TOP w0.508: v1(39.37,11.43) 39.5,11.56 C548.1 C547.1 ; R611.1 R417.1 48.9,30.48 48.64,30.73 v1(48.26,30.73) ; C520.2 R424.1 48.01,36.83 47.5,36.32 47.5,35.15 v1(48.27,34.38) ; U62.7 57.78,38.1 v1(57.15,37.47) 56.64,37.47 R423.1 R425.1 R414.1 R415.1 ; U55.3 57.4,25.4 v1(57.53,25.53) ; C527.1 v1(34.92,40.64) ; R415.1 57.51,33.02 v1(57.91,32.61) ; R415.1 R610.1 R416.1 R422.1 C494.2 ; C539.2 v1(22.86,20.32) ; C471.2 v1(79.38,14.61) ; C694.2 C492.2 56,20.19 56.52,20.7 C493.2 ; C694.2 56.95,19.68 v1(57.12,19.51) ; C694.2 R533.2 ; C523.1 44.32,40.13 v1(43.81,40.64) ; R444.2 v1(43.18,49.91) ; v1(51.98,24.13) C557.1 C552.2 ; v1(8.92,36.45) 9.53,35.84 R538.1 ; C472.2 v1(79.38,13.34) ; C556.1 v1(51.94,26.67) ; v1(33,11.42) 32.38,12.03 C543.1 ; C525.1 v1(38.73,40.64) ; R419.1 v1(38.99,45.21) ; C549.1 v1(45.09,11.43) ; C545.1 34.92,11.68 v1(35.18,11.43) ; C602.2 v1(70.48,44.45) ; v1(71.12,24.13) 70.69,24.13 70.05,23.5 C563.2 ; C531.2 v1(22.86,34.92) ; C550.1 v1(43.81,11.43) ; C542.1 28.7,11.43 v1(28.57,11.43) 28.09,11.91 28.09,12.42 C541.1 ; v1(52.07,21.21) 51.69,21.59 C558.1 C559.1 ; C544.1 33.66,11.87 v1(34.1,11.42) ; C406.1 v1(20.95,13.97) ; v1(52.22,33.12) 51.03,33.12 C553.1 C392.2 ; C529.1 v1(29.84,40.64) ; C561.2 v1(70.47,31.75) ; C378.2 v1(27.3,10.16) ; v1(22.86,22.86) 22.86,23.01 23.35,23.5 C538.2 ; U58.7 v1(60.96,27.94) ; R420.1 C522.1 45.59,40.13 v1(45.09,40.64) ; D89.1 52.39,7.05 v1(53.34,6.1) ; C524.1 v1(40.01,40.64) ; v1(50.16,1.4) 50.04,1.4 49.15,2.28 C592.2 ; v1(40.64,6.1) 40.96,6.42 D127.1 ; v1(45.97,15.24) 46.35,14.86 R701.1 ; C526.1 v1(36.2,40.64) ; Q1.2 6.04,36.11 v1(6.38,36.45) ; R421.1 42.8,40.39 v1(42.55,40.64) ; C554.1 C555.1 51.82,27.94 v1(51.94,27.81) ; v1(71.12,22.1) 69.98,20.95 C564.2 ; C565.2 69.98,22.23 70.87,23.11 v1(71.12,23.11) ; C551.1 v1(42.55,11.43) ; C593.2 45.72,6.81 45.26,6.35 v1(45.09,6.35) ; v1(70.48,34.29) C562.2 C560.2 ; U59.7 60.53,17.14 61.09,16.59 v1(61.09,16.38) ; C505.2 6.23,27.46 v1(6.24,27.44) ; v1(36.2,6.35) 36.2,6.6 36.83,7.24 C699.2 ; R448.2 v1(19.05,13.97) ; C696.2 v1(52.07,17.78) ; C536.2 v1(22.86,28.57) ; R445.2 v1(44.45,49.91) ; C601.2 v1(70.48,41.91) ; v1(22.84,29.62) 23.07,29.84 C535.2 C534.2 C533.2 C532.2 22.99,33.66 v1(22.86,33.78) ; v1(75.18,22.73) 75.56,22.73 C447.1 ; R418.1 v1(41.27,40.64) ; C519.2 v1(19.06,32.38) ; D95.1 14.93,36.51 v1(15.24,36.2) ; R703.1 v1(27.43,45.09) ; R588.2 v1(54.48,51.57) ; C409.2 v1(17.78,13.97) ; C600.2 v1(70.48,43.18) ; v1(52.07,19.94) 51.18,19.05 C521.2 ; R410.1 v1(28.57,10.16) ; v1(56.97,10.64) 57.15,10.46 C452.2 ; R443.2 v1(41.91,49.91) ; C546.1 v1(36.83,11.43) ; R707.1 22.99,36.2 ; C528.1 v1(33.66,40.64) ; C530.1 v1(28.57,40.64) ; C537.2 v1(22.86,27.3)
  BOTTOM w0.254: U28.51 45.22,11.56 v1(45.09,11.43) ; U28.32 51.99,21.28 v1(52.07,21.21) 51.15,20.28 U28.34 ; v1(45.97,15.24) 45.71,14.98 U28.50 ; D92.1 55.86,25.71 55.7,25.55 55.7,24.69 55.17,24.16 55.17,23.52 55.68,23.01 55.68,22.81 C408.2 ; U28.52 44.71,12.33 v1(43.81,11.43) ; U28.33 48.68,20.79 v1(48.26,21.21)
  BOTTOM w0.381: D115.1 54.29,6.94 53.44,6.1 v1(53.34,6.1) ; v1(62.23,21.59) 62.1,21.72 R697.1 C700.2 ; v1(61.09,16.38) 61.07,16.4 60.31,16.4 59.44,17.27 R699.1 C701.2 ; U57.6 7.93,27.96 v1(7.42,27.45) ; U57.9 9.88,27.97 v1(10.41,27.44) ; U43.5 75.69,22.23 v1(75.18,22.73) ; R695.1 C698.2 R692.2 16,40.13 16.63,40.76 v1(16.89,40.76)
  BOTTOM w0.508: v1(45.09,6.35) 45.09,6.63 44.45,7.26 C595.2 43.69,7.5 43.44,7.25 D90.1 ; C691.1 R681.1 60.45,12.58 v1(60.96,12.06) ; C396.2 68.07,29.09 v1(67.94,29.21) v1(67.94,26.42) ; v1(19.05,29.72) C254.1 ; v1(49.15,6.1) 49.53,6.48 C687.1 R673.1 ; U32.3 v1(65.41,26.42) ; v1(66.8,15.88) 65.79,15.88 64.14,17.53 U45.4 ; U45.5 64.14,22.99 65.66,21.46 v1(66.67,21.46) 67.06,21.08 69.6,21.08 C451.2 ; D92.1 57.34,25.71 v1(57.53,25.53) 58.42,26.42 C410.2 ; v1(74.93,24.13) 74.3,23.5 R484.1 C448.1 ; C694.2 56.95,19.68 v1(57.12,19.51) ; D85.1 57.09,28.89 v1(57.28,28.7) ; 76.89,33.66 v1(74.93,33.66) ; C407.2 v1(75.56,1.27) ; C597.2 36.58,6.73 v1(36.2,6.35) 35.66,6.35 35.24,6.77 D86.1 ; C463.2 74.81,34.8 v1(74.93,34.92) ; v1(55.82,6.35) 55.88,6.41 C489.2 ; R446.2 v1(76.83,1.27) ; v1(57.15,37.47) C695.2 C693.2 ; v1(52.96,15.11) 53.34,14.73 C690.1 R680.1 ; C371.1 v1(19.05,34.41) ; U53.4 v1(79.38,19.05) ; C464.2 v1(71.12,31.11) ; v1(37.47,6.35) 37.98,6.86 C596.2 ; v1(64.14,26.42) U32.4 ; D84.1 57.06,32.06 57.61,32.61 v1(57.91,32.61) ; C405.2 v1(78.11,1.27) ; U61.3 v1(75.03,28.57) ; U32.2 v1(66.67,26.42) ; v1(56.52,14.61) 56,15.12 C598.2
  vias: v1(2.54,11.43) v1(2.54,10.16) v1(2.54,8.89) v1(3.81,11.43) v1(3.81,10.16) v1(3.81,8.89) v1(4.45,27.3) v1(4.45,26.04) v1(4.45,24.77) v1(5.08,37.47) v1(5.11,36.45) v1(5.71,26.04) v1(6.35,37.47) v1(7.62,37.47) v1(7.65,36.45) v1(10.19,36.45) v1(11.18,36.45) v1(12.06,27.3) v1(12.06,26.04) v1(12.06,24.77) v1(12.45,5.46) v1(12.45,4.19) v1(13.72,5.46) v1(13.72,4.19) v1(14.61,34.92) v1(14.61,33.02) v1(14.61,31.11) v1(14.61,29.21) v1(14.61,14.61) v1(14.61,12.06) v1(14.61,9.53) v1(14.61,6.99) v1(14.99,5.46) v1(14.99,4.19) v1(15.24,27.3) v1(16.51,36.83) v1(16.51,26.67) v1(17.78,36.2) v1(17.78,27.3) v1(33.15,30.48) v1(33.15,29.21) v1(33.15,27.94) v1(33.15,26.67) v1(33.15,25.4) v1(33.15,24.13) v1(33.15,22.86) v1(34.29,30.48) v1(34.29,29.21) v1(34.29,27.94) v1(34.29,26.67) v1(34.29,25.4) v1(34.29,24.13) v1(34.29,22.86) v1(35.56,30.48) v1(35.56,29.21) v1(35.56,27.94) v1(35.56,26.67) v1(35.56,25.4) v1(35.56,24.13) v1(35.56,22.86) v1(36.83,30.48) v1(36.83,29.21) v1(36.83,27.94) v1(36.83,26.67) v1(36.83,25.4) v1(36.83,24.13) v1(36.83,22.86) v1(38.1,30.48) v1(38.1,29.21) v1(38.1,27.94) v1(38.1,26.67) v1(38.1,25.4) v1(38.1,24.13) v1(38.1,22.86) v1(39.37,30.48) v1(39.37,29.21) v1(39.37,27.94) v1(39.37,26.67) v1(39.37,25.4) v1(39.37,24.13) v1(39.37,22.86) v1(40.64,30.48) v1(40.64,29.21) v1(40.64,27.94) v1(40.64,26.67) v1(40.64,25.4) v1(40.64,24.13) v1(40.64,22.86) v1(41.78,30.48) v1(41.78,29.21) v1(41.78,27.94) v1(41.78,26.67) v1(41.78,25.4) v1(41.78,24.13) v1(41.78,22.86) v1(46.99,1.27) v1(51.44,1.4) v1(52.7,1.4) v1(59.69,1.4) v1(60.96,1.4) v1(62.23,24.13) v1(66.04,1.27) v1(67.31,1.27) v1(68.58,1.27) v1(69.85,1.27)
SGND: length 33.2
  TOP w0.381: C453.1 v1(98.93,27.3) ; R508.2 v1(98.93,28.57) ; C467.2 v1(98.93,29.84) ; R489.1 v1(98.93,26.04)
  TOP w0.508: v1(92.59,39.12) R497.2 C459.2 ; R494.1 92.97,23.12 v1(92.71,22.86) ; C237.1 R133.2 89.41,25.91 v1(88.9,25.4) ; v1(92.45,30.77) 92.45,30.56 93.17,29.84 C465.2 ; C458.2 v1(98.42,36.83)
  BOTTOM w0.381: v1(96.9,22.73) 92.84,22.73 v1(92.71,22.86) ; 97.79,25.4 U44.4 ; C445.1 92.35,27.3 92.58,27.53 v1(92.58,27.94) ; U48.4 97.16,34.42 v1(97.03,34.29)
  BOTTOM w0.508: C457.2 v1(88.9,22.23) U43.4 ; 87.29,23.5 v1(88.9,23.5) ; v1(92.71,22.86) 92.51,22.86 91.87,23.5 C446.2 ; C462.2 C566.2 91.6,31.62 v1(92.45,30.77) ; R575.2 97.16,41.02 ; C594.2 95.89,41.02 ; v1(98.3,22.65) 97.79,22.14 U44.5
VDD: length 32.8
  TOP w0.508: C548.2 40.64,15.24 v1(40.64,15.24) ; C522.2 45.59,37.08 v1(45.34,36.83) ; C535.1 v1(26.67,29.84) ; v1(26.67,33.93) 26.39,33.66 C532.1 ; C526.2 v1(36.2,36.83) ; v1(48.26,26.67) C556.2 ; C554.2 49.02,28.83 v1(48.26,28.83) ; C543.2 v1(32.38,15.24) ; C530.2 28.57,36.96 v1(28.45,36.83) ; C525.2 v1(38.73,36.83)
  BOTTOM w0.254: v1(48.26,26.67) 48.38,26.79 U28.21 ; v1(40.64,15.24) 40.22,14.82 U28.61 ; U28.158 39.22,37.31 v1(38.73,36.83) ; U28.16 49.2,29.28 48.74,28.83 v1(48.26,28.83) ; U28.153 36.71,37.35 v1(36.2,36.83) ; v1(28.45,36.83) 28.71,37.1 U28.137 ; v1(26.67,29.84) 26.11,29.28 U28.117 ; v1(45.34,36.83) 44.71,37.45 U28.169 ; v1(32.38,15.24) 32.71,14.91 U28.76 ; v1(26.67,33.93) 26.52,33.79 U28.126
  vias: v1(8.13,5.46) v1(8.13,4.19) v1(9.4,5.46) v1(9.4,4.19) v1(10.67,5.46) v1(10.67,4.19)
/TRST_P: length 13.8
  TOP w0.152: J5.2 26.67,5.71 27.3,6.35 C378.1 R410.2 v1(28.57,6.35)
  BOTTOM w0.152: v1(28.57,6.35) 30.54,8.31 30.54,10.47 31.22,11.14 U28.79
/WP_PFC: length 32.4
  ART03 w0.127: v1(67.94,39.37) 67.31,38.73 65.79,38.73 65.15,38.1 60.71,38.1 58.21,40.6 47.96,40.6 v1(47.88,40.68)
  BOTTOM w0.152: v1(67.94,39.37) 68.45,38.86 68.45,38.27 69,37.72 69.09,37.72 69.34,37.47 69.34,35.69 69.09,35.44 R439.1 68.28,35.13 68.28,34.9 67.84,34.47 67.06,34.47 66.67,34.09 U32.7 ; U28.175 47.71,39.88 47.88,40.04 v1(47.88,40.68)
_AC_LA_ADC: length 6.1
  BOTTOM w0.152: R432.1 C393.1 53.87,15.62 52.71,16.79 U28.41
_AC_LA_OC: length 5.4
  TOP w0.508: v1(48.26,33.02) 48.26,33.4 49.15,34.29 C392.1 R431.1
  BOTTOM w0.152: U28.7 49.03,33.79 v1(48.26,33.02)
_AC_LB_ADC: length 5.9
  BOTTOM w0.152: C694.1 R684.1 51.94,18.41 51.31,17.79 U28.39
_AC_LB_OC: length 6.8
  BOTTOM w0.152: U28.9 50.95,32.79 51.41,33.25 51.41,33.49 51.83,33.92 52.53,33.92 52.83,34.21 52.83,34.5 53.13,34.8 53.64,34.8 53.77,34.92 R683.1 C693.1
_AC_LC_ADC: length 6.2
  TOP w0.152: C696.1 R686.1 48.26,16.51 v1(46.99,15.24)
  BOTTOM w0.152: U28.48 46.71,14.96 v1(46.99,15.24)
_AC_LC_OC: length 50.7
  TOP w0.152: R689.1 C697.1 18.41,44.04 20.32,45.95 v1(20.32,46.35)
  ART03 w0.127: v1(52.07,34.47) 50.83,35.71 43.13,35.71 40.44,38.4 29.79,38.4 27.94,40.26 27.94,40.89 27.56,41.27 26.27,41.27 25.58,41.96 23.19,41.96 21.13,44.02 21.13,45.54 v1(20.32,46.35)
  BOTTOM w0.152: U28.8 50.91,33.28 51.12,33.49 51.12,33.67 51.71,34.26 51.87,34.26 v1(52.07,34.47) 52.15,34.54 52.4,34.54 52.93,35.08 53.53,35.08 53.72,35.27 53.72,36.7 C695.1 R608.1
_AD_DCINPUT: length 12.6
  TOP w0.152: R529.2 48.9,10.41 v1(47.88,11.43)
  BOTTOM w0.152: U28.46 47.71,11.59 v1(47.88,11.43) 49.15,10.16 52.7,10.16 53.34,9.53 D115.3 53.49,9.12 55.78,9.12 C489.1
_AD_DCINPUT_OV: length 13
  TOP w0.152: C699.1 R693.2 v1(38.1,11.43)
  BOTTOM w0.152: U28.60 40.71,12.39 40.39,12.06 38.73,12.06 v1(38.1,11.43) 37.47,10.79 34.67,10.79 34.29,10.41 D86.3
_AD_DCTEMP: length 9
  BOTTOM w0.152: D92.3 53.85,24.77 53.59,24.51 53.59,23.88 54.49,22.98 C408.1 R447.2 53.34,21.21 52.77,21.78 50.15,21.78 U28.31
_AD_SRTEMP: length 20
  BOTTOM w0.152: U28.29 51.69,22.79 51.89,22.58 52.32,22.58 52.68,22.94 52.68,25.3 53.24,25.86 53.24,29.26 53.59,29.62 53.59,30.91 53.8,31.11 D84.3 54.71,31.11 55.09,30.73 55.09,28.6 55.5,28.19 57.91,28.19 C410.1 R449.2
AC_LA_ADC: length 66.6
  TOP w0.152: v1(51.99,23.24) 52.7,22.53 52.7,18.52 53.57,17.65 53.61,17.65 53.63,17.63 56.67,17.63 v1(57.15,17.14)
  ART03 w0.127: v1(51.99,23.24) 50.77,23.24 38.2,35.81 27.35,35.81 26.54,36.62 26.54,39.5 24.89,41.15 22.1,41.15 19.05,44.2 19.05,47.32 21.46,49.73 21.46,50.67 20.7,51.44 19.06,51.44 J2.15
  BOTTOM w0.152: v1(57.15,17.14) 56.9,16.89 R432.2
AC_LA_OC: length 42.3
  TOP w0.152: v1(52.07,35.81) 51.82,35.56 R431.2 ; D124.3 R688.2 26.29,42.42 v1(26.42,42.29) 26.42,46.1 27.94,47.62 J2.8
  ART03 w0.127: v1(26.42,42.29) 27.37,43.24 29.84,43.24 31.37,41.71 31.37,41.15 33.6,38.91 40.51,38.91 43.23,36.2 51.69,36.2 v1(52.07,35.81)
AC_LAB_SENSE_ADC: length 6.9
  BOTTOM w0.152: AB.1 64.14,14.61 62.23,16.51 R706.1 R698.1
AC_LB_ADC: length 72.1
  TOP w0.152: v1(52.07,25.4) 53.06,24.41 53.06,18.59 53.75,17.91 56.92,17.91 57.15,18.14 v1(57.15,18.54)
  ART03 w0.127: v1(52.07,25.4) 50.14,27.33 47.73,27.33 38.79,36.27 27.25,36.27 26.87,36.65 26.87,39.78 25.15,41.5 22.71,41.5 19.61,44.6 19.61,46.91 21.77,49.07 21.77,52.91 20.85,53.82 16.36,53.82 15.25,52.71 J2.17
  BOTTOM w0.152: R684.2 57.02,18.41 v1(57.15,18.54)
AC_LB_OC: length 53.1
  TOP w0.152: J2.10 25.4,47.12 23.5,45.21 v1(23.5,42.55) 23.37,42.42 R685.2 D125.3
  ART03 w0.127: v1(23.5,42.55) 25.4,44.45 29.72,44.45 32.51,41.66 32.51,41.02 34.06,39.47 40.54,39.47 42.65,37.36 52.3,37.36 52.6,37.66 52.6,38.04 52.91,38.35 54.25,38.35 56.41,36.2 v1(57.15,36.2)
  BOTTOM w0.152: R683.2 56.52,34.92 57.15,35.56 v1(57.15,36.2)
AC_LBC_SENSE_ADC: length 15
  BOTTOM w0.152: BC.1 66.67,13.84 63.37,17.14 63.37,19.05 63.75,19.43 63.75,20.32 62.87,21.21 62.87,21.84 62.48,22.23 61.72,22.23 R696.1 R704.1
AC_LC_ADC: length 93.2
  TOP w0.152: v1(53.98,11.38) 54.69,11.38 55.12,11.81 55.12,14.61 54.86,14.86 53.98,14.86 53.02,15.81 52.51,15.81 52.2,15.49 52.2,15.11 51.94,14.86 51.18,14.86 50.92,15.12 R686.2
  ART03 w0.127: J2.19 13.92,51.49 13.92,42.42 13.72,42.21 13.72,16.74 18.31,12.14 22.28,12.14 25.6,8.81 36.78,8.81 38.86,10.9 38.86,11.71 39.34,12.19 53.16,12.19 v1(53.98,11.38)
AC_LC_OC: length 52.5
  TOP w0.152: D126.3 19.05,41.15 R687.2 20.78,42.42 21.02,42.66 21.02,45.15 22.86,46.99 J2.12
  ART03 w0.127: J2.12 25.79,47.24 29.46,47.24 33.53,43.18 41.5,43.18 43.23,41.45 43.23,40.34 44.35,39.22 56.41,39.22 56.9,38.73 v1(57.15,38.73)
  BOTTOM w0.152: R608.2 v1(57.15,38.73)
AC_LCA_SENSE_ADC: length 23.7
  TOP w0.152: R705.1 R700.1 50.49,11.76 v1(50.16,11.43)
  BOTTOM w0.152: v1(50.16,11.43) 50.16,11.3 50.8,10.67 53.34,10.67 53.72,10.29 55.88,10.29 57.1,11.51 63.17,11.51 63.63,11.05 67.56,11.05 CA.1
AD_AIR_TEMP: length 16.2
  TOP w0.152: v1(55.06,25.53) 55.24,25.34 R534.2 C493.1
  BOTTOM w0.152: v1(55.06,25.53) 55.24,25.71 55.24,27.56 54.86,27.94 D85.3 53.85,27.94 53.66,27.75 53.66,25.69 53.09,25.12 53.09,22.73 52.64,22.28 U28.30
AD_DCVOLT1: length 11.6
  TOP w0.152: v1(52.37,11.43) 53.34,10.46 D89.3 53.34,9.55 53.72,9.17 54.23,9.17 55.27,8.13 R487.2 C452.1
  BOTTOM w0.152: v1(52.37,11.43) 51.92,11.89 51.56,11.89 50.09,13.36 U28.45
CAN5V_GND: length 53.2
  TOP w0.381: v1(96.76,16.19) 96.64,16.3 96.1,16.3 95.29,15.49 D111.1 95.29,14.69 95.63,14.35 96.66,14.35 v1(96.79,14.48)
  TOP w0.508: 88.88,19.03 v1(88.9,19.05) ; D110.1 88.88,13.42 89.17,13.13 90.77,13.13 v1(91.42,12.48) 91.44,12.51 ; C475.2 v1(87.63,9.53) ; C473.2 v1(86.36,9.53) ; C474.2 v1(88.9,9.53)
  ART03 w0.508: 86.23,18.92 86.23,38.73 87.62,40.12 87.62,50.92 88.14,51.44 92.72,51.44 J4.11
  BOTTOM w0.508: U53.5 v1(88.9,19.05)
CAN_5V: length 51.4
  TOP w0.508: v1(91.44,10.41) 90.43,10.41 R516.1
  ART03 w0.508: v1(87.5,20.95) 87.02,21.44 87.02,38 88.77,39.75 88.77,42.42 95.5,49.15 95.5,51.19 J4.12
  BOTTOM w0.508: v1(91.44,10.41) 92.2,11.18 92.2,18.16 90.3,20.07 88.39,20.07 v1(87.5,20.95)
CANRX: length 64.9
  ART03 w0.127: v1(72.39,17.78) 62.48,17.78 59.12,21.15 59.12,21.4 58.04,22.48 54.36,22.48 52.58,20.7 48.01,20.7 47.4,20.09 45.31,20.09 44.29,19.06 29.27,19.06 24.2,24.13 v1(22.86,24.13)
  BOTTOM w0.152: v1(72.39,17.78) 72.39,17.65 76.07,13.97 U53.2 ; R514.2 v1(22.86,24.13) 23.52,24.79 U28.108
CANTX: length 64.4
  ART03 w0.127: v1(22.86,25.4) 23.58,24.68 24.45,24.68 29.54,19.58 43.84,19.58 44.89,20.64 47.37,20.64 47.76,21.03 47.76,21.46 48.09,21.79 52.52,21.79 53.59,22.86 58.42,22.86 59.42,21.86 59.42,21.35 62.48,18.29 73.15,18.29 v1(73.66,17.78)
  BOTTOM w0.152: R515.2 v1(22.86,25.4) 22.98,25.28 U28.109 ; U53.3 74.8,16.51 73.66,17.65 v1(73.66,17.78)
CS: length 104.3
  TOP w0.152: v1(76.83,17.78) 77.47,18.41 77.47,33.4 73.15,37.72 73.15,48.64 70.36,51.44 58.41,51.44 J3.1 ; R583.1 44.45,6.99 v1(43.81,6.35)
  TOP w0.508: R582.2 R581.2 R580.2 54.48,52.84 J3.1
  ART03 w0.127: v1(43.81,6.35) 46.74,9.27 70.1,9.27 71.25,10.41 74.68,10.41 76.83,12.57 v1(76.83,17.78)
CS_ADC: length 15.5
  TOP w0.152: C593.1 R583.2 v1(43.05,9.01) 42.8,9.26 D127.3
  BOTTOM w0.152: U28.56 42.71,12.4 43.18,11.94 43.18,10.03 42.93,9.78 42.93,9.14 v1(43.05,9.01) 44.2,10.16 46.1,10.16 46.41,9.86 46.41,7.67 46.23,7.5 R599.1
CS_PRI: length 76.8
  TOP w0.152: v1(40.56,9.98) 39.6,9.01 R602.1
  TOP w0.381: J2.18 12.83,47.76 v1(12.83,45.13) R603.2 R604.2 R605.2
  ART03 w0.127: v1(12.83,45.13) 12.95,45 12.95,15.33 17.08,11.2 21.79,11.2 24.94,8.05 37.52,8.05 38.96,9.5 38.96,10.06 39.45,10.54 40.26,10.54 40.56,10.24 v1(40.56,9.98)
CS_RTN: length 14
  TOP w0.508: J3.3 58.42,48.9 56.63,48.9 55.49,50.05 R588.1 52.63,50.05 52.62,50.04 R580.1 R581.1 R582.1
CS_RTN_PRI: length 15.5
  TOP w0.381: J2.20 11.56,49.03 11.56,46.35 10.03,44.83 R603.1 R604.1 R605.1 9.01,38.1 R702.1
DC-OV: length 11.7
  TOP w0.381: J2.22 10.16,46.74 8.51,45.09 v1(8.51,40.77)
  BOTTOM w0.381: R694.2 v1(8.51,40.77)
DC_FB: length 4.7
  BOTTOM w0.152: J2.24 5.58,52.21 R49.2
DCOVP: length 35.9
  ART03 w0.127: v1(69.22,39.37) 68.55,40.03 65.94,40.03 64.77,38.86 62.48,38.86 61.31,40.03 60.04,40.03 58.8,41.27 49.02,41.27 48.51,41.78 v1(47.88,41.78)
  BOTTOM w0.152: U60.4 73.78,36.2 C463.1 R502.2 69.34,39.37 v1(69.22,39.37) ; v1(47.88,41.78) 48.64,41.02 48.64,39.75 48.22,39.33 U28.176
DCPWM1A_1H: length 29.1
  TOP w0.152: v1(62.23,31.75) 62.23,31.24 60.83,29.84 60.83,29.34 60.71,29.21 U58.6
  BOTTOM w0.152: v1(62.23,31.75) 61.72,32.26 61.72,36.27 64.9,39.45 64.9,45.59 60.96,49.53 60.96,51.18 59.69,52.45 J3.4
DCPWM1A_1HH: length 35.2
  TOP w0.152: R419.2 40.01,42.19 v1(39.47,41.66) ; U58.5 60.71,30.48 61.47,31.24 61.47,32.51 v1(60.96,33.02)
  ART03 w0.127: v1(60.96,33.02) 60.96,33.15 57.15,36.96 56.72,36.96 55.07,38.61 42.57,38.61 40.64,40.54 40.64,41.02 40.01,41.66 v1(39.47,41.66)
  BOTTOM w0.152: U28.160 40.22,39.58 39.47,40.32 v1(39.47,41.66)
DCPWM1A_1L: length 28.1
  TOP w0.152: U58.4 v1(60.96,31.75)
  BOTTOM w0.152: J3.2 57.15,52.7 58.42,51.44 58.42,49.28 59.56,48.13 60.83,48.13 64.52,44.45 64.52,39.62 60.45,35.56 60.45,32.26 v1(60.96,31.75)
DCPWM1A_1LL: length 34
  TOP w0.152: U58.3 60.07,33.02 60.96,33.91 v1(60.96,34.29) ; v1(42.04,41.78) 42.04,38.23 41.79,37.98 R418.2
  ART03 w0.127: v1(42.04,41.78) 42.01,41.75 42.01,40.29 43.36,38.94 55.73,38.94 56.44,38.23 57.28,38.23 60.96,34.54 v1(60.96,34.29)
  BOTTOM w0.152: U28.162 41.22,39.65 40.64,40.23 40.64,40.9 41.08,41.34 41.6,41.34 v1(42.04,41.78)
DCPWM2A_2H: length 21.9
  TOP w0.152: U58.12 v1(62.23,33.02)
  BOTTOM w0.152: J3.7 65.91,49.03 65.91,39.37 62.87,36.32 62.87,33.66 v1(62.23,33.02)
DCPWM2A_2HH: length 37.1
  TOP w0.152: R420.2 47.5,37.98 47.68,38.15 47.68,40 47.5,40.18 47.49,40.18 47.37,40.3 47.37,40.89 47.12,41.15 46.35,41.15 v1(45.72,41.78) ; v1(62.23,34.29) 62.78,33.74 63.84,33.74 64.4,34.29 U58.13
  ART03 w0.127: v1(62.23,34.29) 61.47,35.05 61.47,37.08 61.02,37.53 60.01,37.53 57.71,39.83 46.66,39.83 45.72,40.77 v1(45.72,41.78)
  BOTTOM w0.152: v1(45.72,41.78) 44.45,41.78 43.94,42.29 43.31,42.29 41.99,40.97 41.99,39.85 42.22,39.62 U28.164
